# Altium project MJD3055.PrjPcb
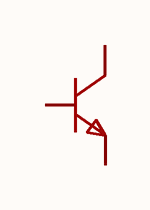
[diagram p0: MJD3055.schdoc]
1 sheet, 1 parts. Net scope: global (net labels, ports and power ports of the same name join across sheets).

## Sheet MJD3055.schdoc
size 127 x 101 mm

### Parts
Q?  mjd3055  [TO-252-2_L6.6-W6.1-P4.57-LS10.0-BR-1]  (value not drawn)

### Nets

Not connected (* = marked no-connect by the designer): Q? 1(B) 2(C) 3(E)

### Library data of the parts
Q? = mjd3055: 晶体管类型:NPN;集电极电流(Ic):10A;集射极击穿电压(Vceo):60V;耗散功率(Pd):1.25W;直流电流增益(hFE):20;; Manufacturer: CJ(江苏长电/长晶); AddInBom: yes; ModelId: 4113ec4a058842b08e2585e7304bd9b4; ModelTransform: 401.574,259.842,0,0,0,0,-36.417,0,0; type: NPN; Current - Collector(Ic): 10A; Collector - Emitter Voltage VCEO: 60V; Pd - Power Dissipation: 1.25W; DC Current Gain: 20; Transition frequency(fT): 2MHz; Current - Collector Cutoff: 20uA; Vce Saturation(VCE(sat)): 8V; Emitter-Base Voltage(Vebo): 5V; Number: 1个NPN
